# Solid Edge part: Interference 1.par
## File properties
Last saved by: Ilambrescu
Revision: 59
Accuracy: 0.990
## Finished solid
Body 1: solid body, 5 faces, 7 edges, 4 vertices.
  Faces by surface: plane 3, cylinder 2
  Edges by curve: circle 5, line 2
Bounding box of the edges (mm): 4.000 x 4.000 x 4.000, from (-2, -4.7321, 6) to (2, -0.7321, 10).
Cylindrical faces by radius (mm): R2 x2
Planar faces by outward normal: +z 2, -z 1
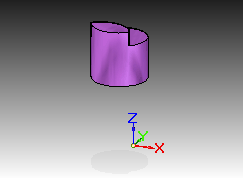
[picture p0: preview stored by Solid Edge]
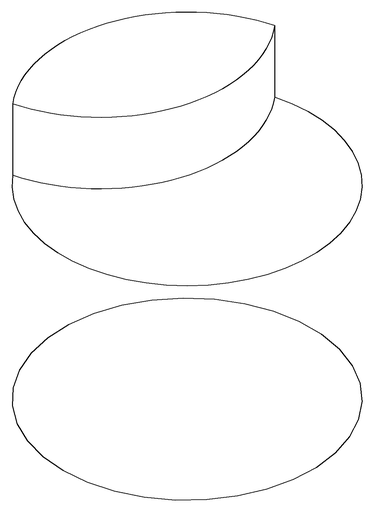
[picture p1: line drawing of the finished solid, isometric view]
